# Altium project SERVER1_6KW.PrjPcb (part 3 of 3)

## Sheet 7.SchDoc
size 420 x 297 mm
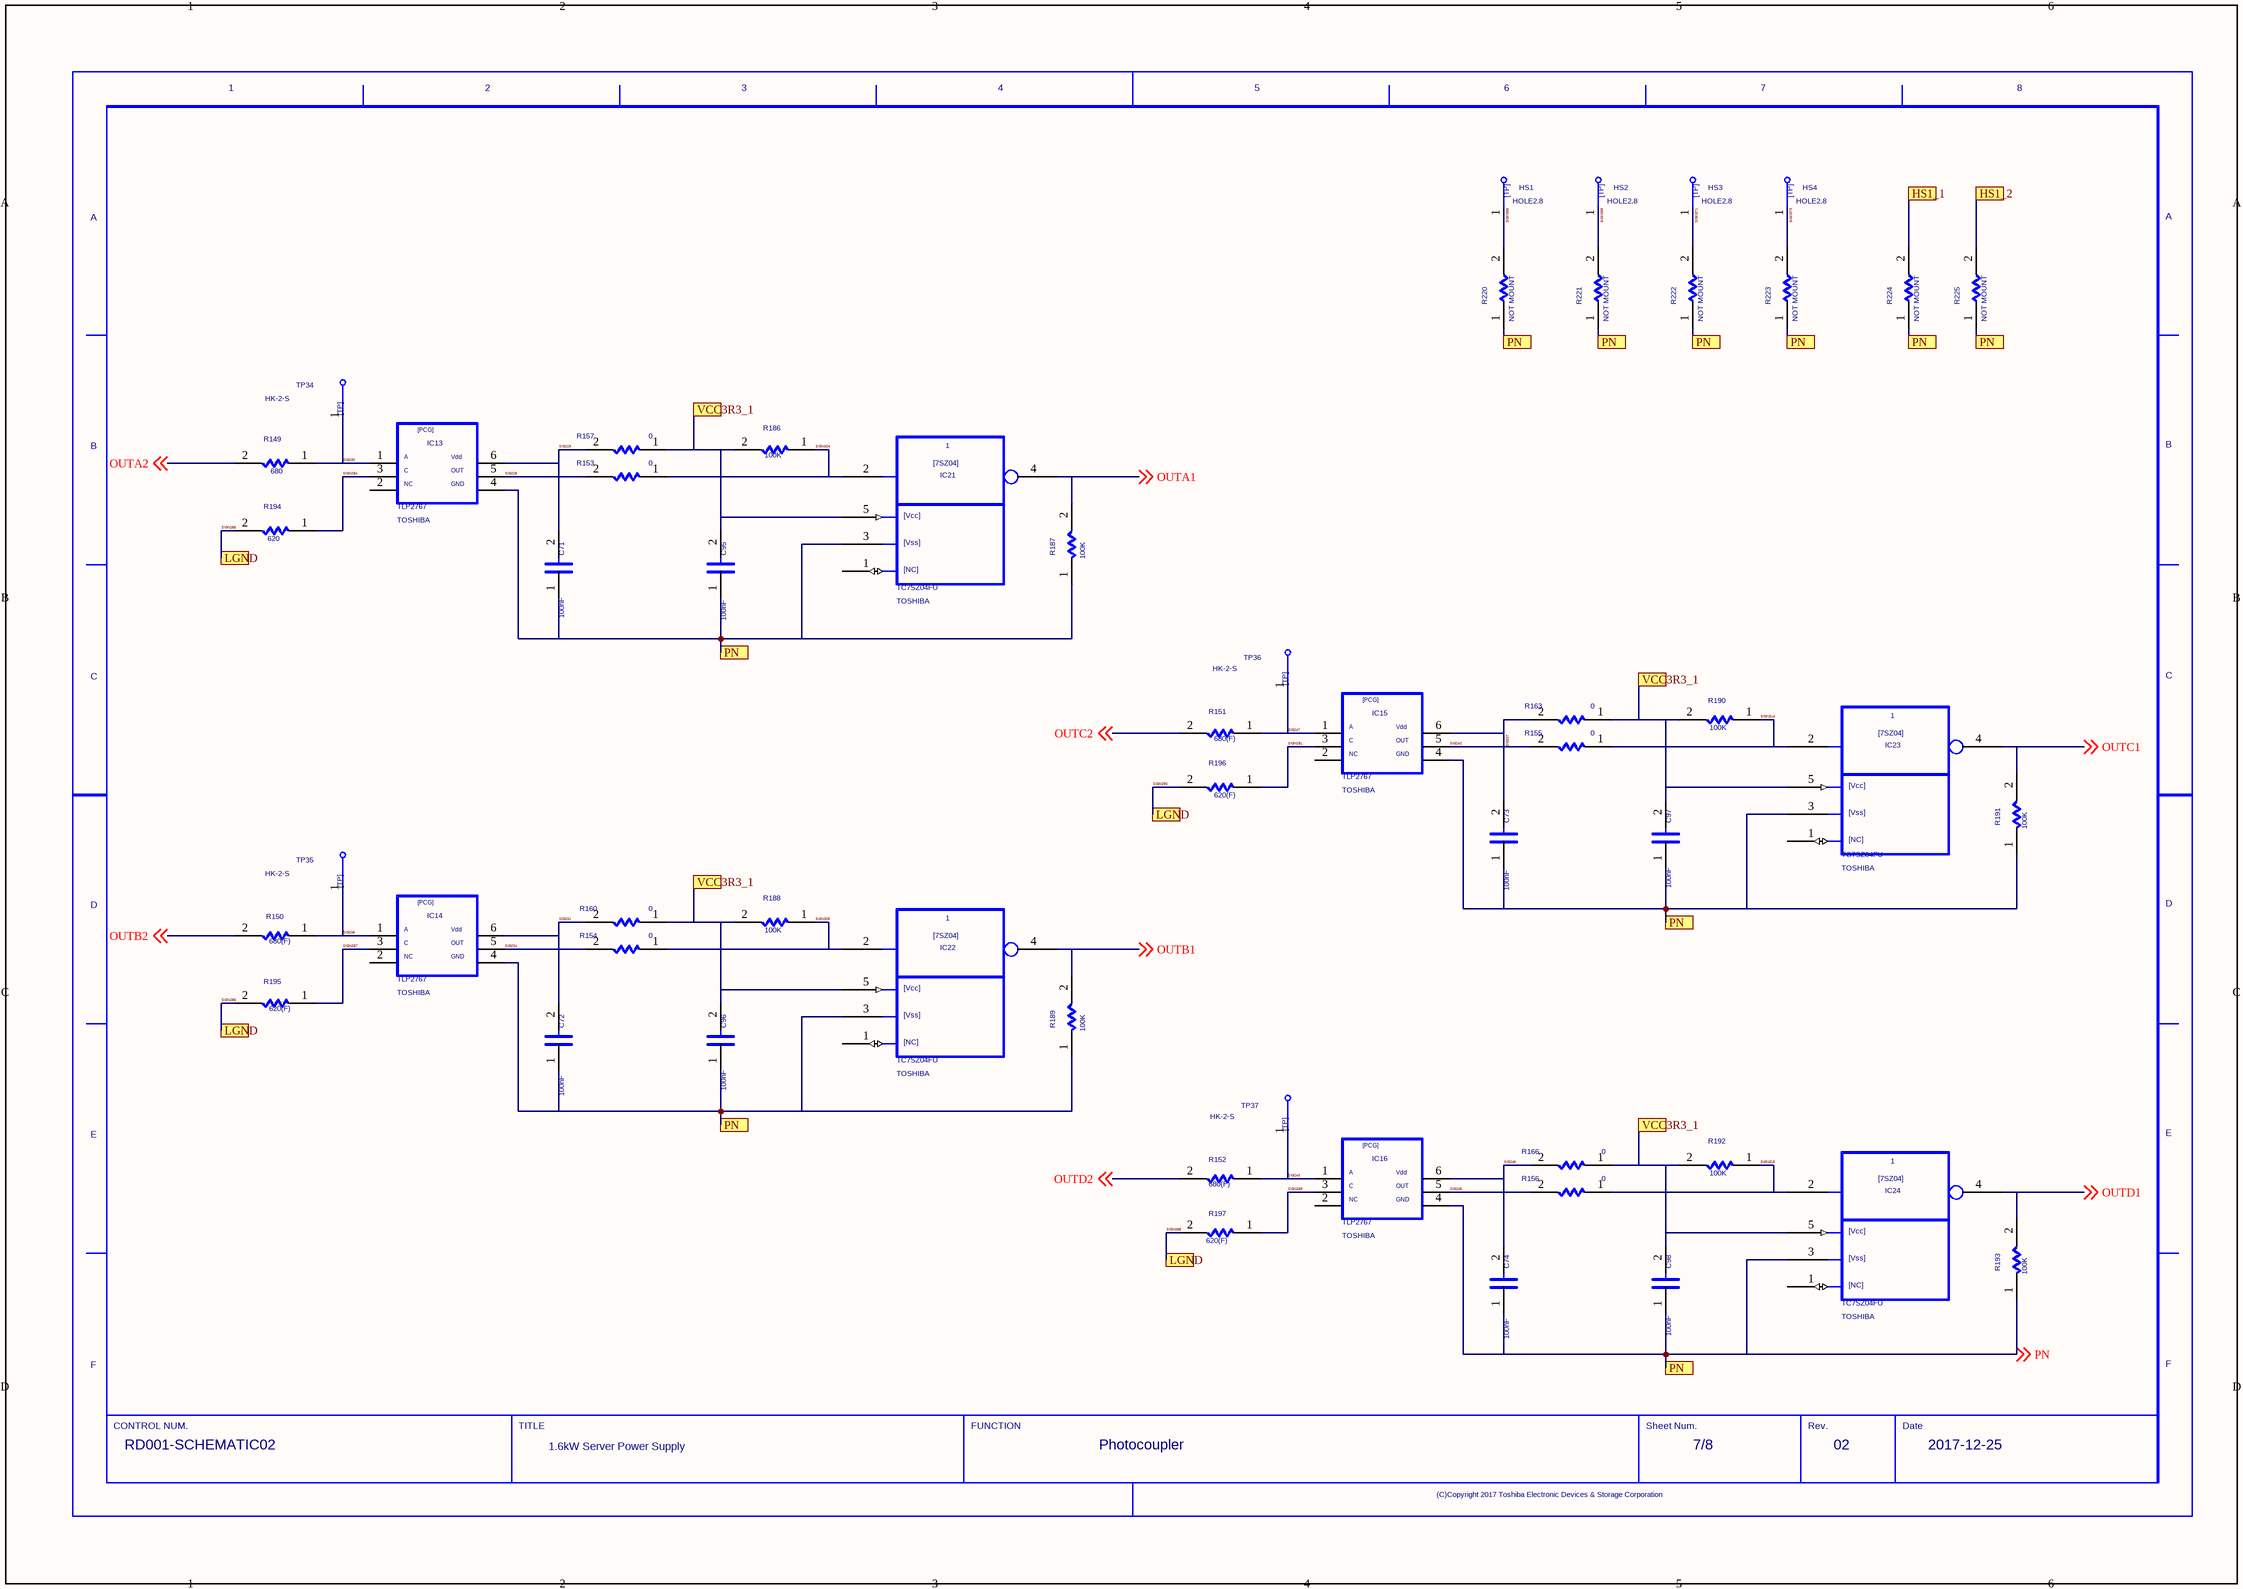
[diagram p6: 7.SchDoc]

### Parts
(Parts that share a designator on the sheet are numbered #1, #2 ... from top to bottom, then left to right.)
C71  VAL1: 100nF  (hidden comment: C)
C72  VAL1: 100nF  (hidden comment: C)
C73  VAL1: 100nF  (hidden comment: C)
C74  VAL1: 100nF  (hidden comment: C)
C95  VAL1: 100nF  (hidden comment: C)
C96  VAL1: 100nF  (hidden comment: C)
C97  VAL1: 100nF  (hidden comment: C)
C98  VAL1: 100nF  (hidden comment: C)
HS1  VAL3: HOLE2.8  (hidden comment: TP)
HS2  VAL3: HOLE2.8  (hidden comment: TP)
HS3  VAL3: HOLE2.8  (hidden comment: TP)
HS4  VAL3: HOLE2.8  (hidden comment: TP)
IC13  USERCOMPTEXT3: TOSHIBA  VAL3: TLP2767  (hidden comment: PCG6PIN)
IC14  USERCOMPTEXT3: TOSHIBA  VAL3: TLP2767  (hidden comment: PCG6PIN)
IC15  USERCOMPTEXT3: TOSHIBA  VAL3: TLP2767  (hidden comment: PCG6PIN)
IC16  USERCOMPTEXT3: TOSHIBA  VAL3: TLP2767  (hidden comment: PCG6PIN)
IC21  USERCOMPTEXT3: TOSHIBA  VAL3: TC7SZ04FU  (hidden comment: 7SZ04)
IC22  USERCOMPTEXT3: TOSHIBA  VAL3: TC7SZ04FU  (hidden comment: 7SZ04)
IC23  USERCOMPTEXT3: TOSHIBA  VAL3: TC7SZ04FU  (hidden comment: 7SZ04)
IC24  USERCOMPTEXT3: TOSHIBA  VAL3: TC7SZ04FU  (hidden comment: 7SZ04)
R149  VAL1: 680  (hidden comment: R)
R150  VAL1: 680(F)  (hidden comment: R)
R151  VAL1: 680(F)  (hidden comment: R)
R152  VAL1: 680(F)  (hidden comment: R)
R153  VAL1: 0  (hidden comment: R)
R154  VAL1: 0  (hidden comment: R)
R155  VAL1: 0  (hidden comment: R)
R156  VAL1: 0  (hidden comment: R)
R157  VAL1: 0  (hidden comment: R)
R160  VAL1: 0  (hidden comment: R)
R163  VAL1: 0  (hidden comment: R)
R166  VAL1: 0  (hidden comment: R)
R186  VAL1: 100K  (hidden comment: R)
R187  VAL1: 100K  (hidden comment: R)
R188  VAL1: 100K  (hidden comment: R)
R189  VAL1: 100K  (hidden comment: R)
R190  VAL1: 100K  (hidden comment: R)
R191  VAL1: 100K  (hidden comment: R)
R192  VAL1: 100K  (hidden comment: R)
R193  VAL1: 100K  (hidden comment: R)
R194  VAL1: 620  (hidden comment: R)
R195  VAL1: 620(F)  (hidden comment: R)
R196  VAL1: 620(F)  (hidden comment: R)
R197  VAL1: 620(F)  (hidden comment: R)
R220  NOTMOUNT: NOT MOUNT  (hidden comment: R)
R221  NOTMOUNT: NOT MOUNT  (hidden comment: R)
R222  NOTMOUNT: NOT MOUNT  (hidden comment: R)
R223  NOTMOUNT: NOT MOUNT  (hidden comment: R)
R224  NOTMOUNT: NOT MOUNT  (hidden comment: R)
R225  NOTMOUNT: NOT MOUNT  (hidden comment: R)
TP34  VAL3: HK-2-S  (hidden comment: TP)
TP35  VAL3: HK-2-S  (hidden comment: TP)
TP36  VAL3: HK-2-S  (hidden comment: TP)
TP37  VAL3: HK-2-S  (hidden comment: TP)
U?#7  DATE: 2017-12-25  TITLE: 1.6kW Server Power Supply  REVISION: 02  SHEETNUMBER: 7/8  DRAWINGNUMBER: RD001-SCHEMATIC02  FUNCTION: Photocoupler  (hidden comment: WAKU_DEF100)

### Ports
HS1_1, HS1_2, LGND, PN, VCC3R3_1

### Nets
OUTA1: IC21.4 R187.2 ; off-sheet OUTA1
OUTA2: R149.2 ; off-sheet OUTA2
OUTB1: IC22.4 R189.2 ; off-sheet OUTB1
OUTB2: R150.2 ; off-sheet OUTB2
OUTC1: IC23.4 R191.2 ; off-sheet OUTC1
OUTC2: R151.2 ; off-sheet OUTC2
OUTD1: IC24.4 R193.2 ; off-sheet OUTD1
OUTD2: R152.2 ; off-sheet OUTD2
PN: C71.1 C72.1 C73.1 C74.1 C95.1 C96.1 C97.1 C98.1 IC13.4 IC14.4 IC15.4 IC16.4 IC21.3 IC22.3 IC23.3 IC24.3 R187.1 R189.1 R191.1 R193.1 R220.1 R221.1 R222.1 R223.1 R224.1 R225.1 ; off-sheet PN, port PN  [project net SIGN347]
SIG228: IC13.5 R153.2
SIG229: C71.2 IC13.6 R157.2
SIG230: IC13.1 R149.1 TP34.1
SIG231: C72.2 IC14.6 R160.2
SIG234: IC14.5 R154.2
SIG236: IC14.1 R150.1 TP35.1
SIG237: C73.2 IC15.6 R163.2
SIG242: IC15.5 R155.2
SIG243: IC16.1 R152.1 TP37.1
SIG245: IC16.5 R156.2
SIG246: C74.2 IC16.6 R166.2
SIG247: IC15.1 R151.1 TP36.1
SIGN284: IC13.3 R194.1
SIGN285: R194.2 R195.2 R196.2 R197.2 ; port LGND  [also labelled SIGN286, SIGN288, SIGN290]  [project net SIG439]
SIGN287: IC14.3 R195.1
SIGN289: IC16.3 R197.1
SIGN291: IC15.3 R196.1
SIGN304: IC21.2 R153.1 R186.1
SIGN305: IC22.2 R154.1 R188.1
SIGN314: IC23.2 R155.1 R190.1
SIGN315: IC24.2 R156.1 R192.1
SIGN366: HS1.1 R220.2
SIGN369: HS2.1 R221.2
SIGN371: HS3.1 R222.2
SIGN373: HS4.1 R223.2
VCC3R3_1: C95.2 C96.2 C97.2 C98.2 IC21.5 IC22.5 IC23.5 IC24.5 R157.1 R160.1 R163.1 R166.1 R186.2 R188.2 R190.2 R192.2 ; port VCC3R3_1
NetR224_2: R224.2 ; port HS1_1
NetR225_2: R225.2 ; port HS1_2

Not connected (* = marked no-connect by the designer): IC13 2; IC14 2; IC15 2; IC16 2; IC21 1; IC22 1; IC23 1; IC24 1

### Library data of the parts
C71-C74 = C: SQ_PART_MODEL: CON_100N; OriginalSymbolOrigin: (2540,7620); COMP: PRT_52; VAL3: C1005X7R1E104K050BB; MAKER: TDK; CHIPSIZE: 1005; VAL2: 25V,±10%; RATEDVOLTAGE: 25; MAXGCOUNT: 1; OUMEMAKER: MRT 村田製作所; FNLEADFREETHET1GT2GMCTH1: N_N_N; OUMECLASSIFICATION: セラミックコンデンサ; NOMINALCAPACITA: 100n; ADSCNVFLAG: ON; OUMEMAKERKATAMEI: GRM155R71E104KE14D; ADSCOMPONENTNAME: C_1005; CAPACITANCETOLE: K; CDMASTERCADCELG: KC0005; ADSMODELNAME: s_GRM155R71E104KE14D
C95-C98 = C: OriginalSymbolOrigin: (2540,7620); COMP: PRT_52; VAL3: C1005X7R1E104K050BB; MAKER: TDK; CHIPSIZE: 1005; VAL2: 25V,±10%; RATEDVOLTAGE: 25; MAXGCOUNT: 1; NOMINALCAPACITA: 100n; ADSCOMPONENTNAME: C_1005; CAPACITANCETOLE: K; ADSMODELNAME: s_GRM155R71E104KE14D
HS1-HS4 = TP: TIME: 16:12:21; UPDATEUSER: fukuda-y; UPDATETIME: 16:18:11; SAVECOUNT: 2; SAVEAREA0: -242,-92,12810,7836; OriginalSymbolOrigin: (0,7620); COMP: PRT_39; CHIPSIZE: Through Hole
IC13-IC16 = PCG6PIN: TIME: 11:12:30; UPDATEUSER: s.maruyama; UPDATETIME: 11:21:41; SAVECOUNT: 5; SAVEAREA0: -4197,-437,28946,21425; OriginalSymbolOrigin: (5080,17780); COMP: PRT_15
IC21-IC24 = 7SZ04: SAVEAREA0: -11095,0,51836,33020; TIME: 16:23:49; UPDATEUSER: s.maruyama; UPDATETIME: 20:33:11; SAVECOUNT: 7; OriginalSymbolOrigin: (7620,30480); COMP: PRT_2
R149 = R: OriginalSymbolOrigin: (5080,5080); COMP: PRT_8; VAL3: RK73H1JTTD6800F; MAKER: KOA; CHIPSIZE: 1608; VAL2: 100mW,±1%
R150-R152 = R: OriginalSymbolOrigin: (5080,5080); COMP: PRT_8; VAL3: RK73H1JTTD6800F; MAKER: KOA; CHIPSIZE: 1608; VAL2: 100mW
R153-R157 R160 R163 R166 = R: SQ_PART_MODEL: RES_0; OriginalSymbolOrigin: (5080,5080); COMP: PRT_8; VAL3: RK73Z1JTTD; MAKER: KOA; CHIPSIZE: 1608; VAL2: 100mW; MAXGCOUNT: 1; OUMEMAKER: NAE パナソニックエレクトロニックデバイス; MOUNTINGFORMSMD: SMD; FNLEADFREETHET1GT2GMCTH1: 2_1_N; OUMECLASSIFICATION: 表面実装用固定抵抗器; SIZECODESMD: 1005; RESISTANCETOLER: X; PMPRODUCTSTYPEG: HD1-PC1; ADSCNVFLAG: ON; POWERRATING: 63m; OUMEMAKERKATAMEI: ERJ2GE0R00X; ADSCOMPONENTNAME: R_1005; CDMASTERCADCELG: KC0005; ADSMODELNAME: s_ERJ2GE0R00X
R186-R193 = R: OriginalSymbolOrigin: (5080,5080); COMP: PRT_8; VAL3: RK73B1JTTD104J; MAKER: KOA; CHIPSIZE: 1608; VAL2: 100mW,±5%
R194 = R: OriginalSymbolOrigin: (5080,5080); COMP: PRT_8; VAL3: ERJ-3EKF6200V; MAKER: PANASONIC; CHIPSIZE: 1608; VAL2: 100mW,±1%
R195-R197 = R: OriginalSymbolOrigin: (5080,5080); COMP: PRT_8; VAL3: ERJ-3EKF6200V; MAKER: PANASONIC; CHIPSIZE: 1608; VAL2: 100mW
R220-R225 = R: SQ_PART_MODEL: RES_0; OriginalSymbolOrigin: (5080,5080); COMP: PRT_8; VAL3: RK73Z1JTTD; VAL2: 100mW; MAKER: KOA; CHIPSIZE: 1608; VAL1: 0; MAXGCOUNT: 1; OUMEMAKER: HDK 北陸電気工業; MOUNTINGFORMSMD: SMD; FNLEADFREETHET1GT2GMCTH1: N_N_N; OUMECLASSIFICATION: 表面実装用固定抵抗器; SIZECODESMD: 1005; RESISTANCETOLER: X; ADSCNVFLAG: ON; POWERRATING: 63m; OUMEMAKERKATAMEI: CR10-000V; ADSCOMPONENTNAME: R_1005; CDMASTERCADCELG: KC0005; ADSMODELNAME: s_CR10_000V
TP34-TP37 = TP: TIME: 16:12:21; UPDATEUSER: fukuda-y; UPDATETIME: 16:18:11; SAVECOUNT: 2; SAVEAREA0: -242,-92,12810,7836; OriginalSymbolOrigin: (0,7620); COMP: PRT_44; MAKER: MAC8
U?#7 = WAKU_DEF100: PLOTTIME: HH:MM; SAVEAREA0: -45080,-4508,463680,304612; TIME: 18:12:27; UPDATEUSER: f1043010; UPDATETIME: 13:49:58; SAVECOUNT: 3; OriginalSymbolOrigin: (10160,284480); PAGENUMBER: 7; DESIGNED: TOSHIBA

## Sheet 8.SchDoc
size 420 x 297 mm
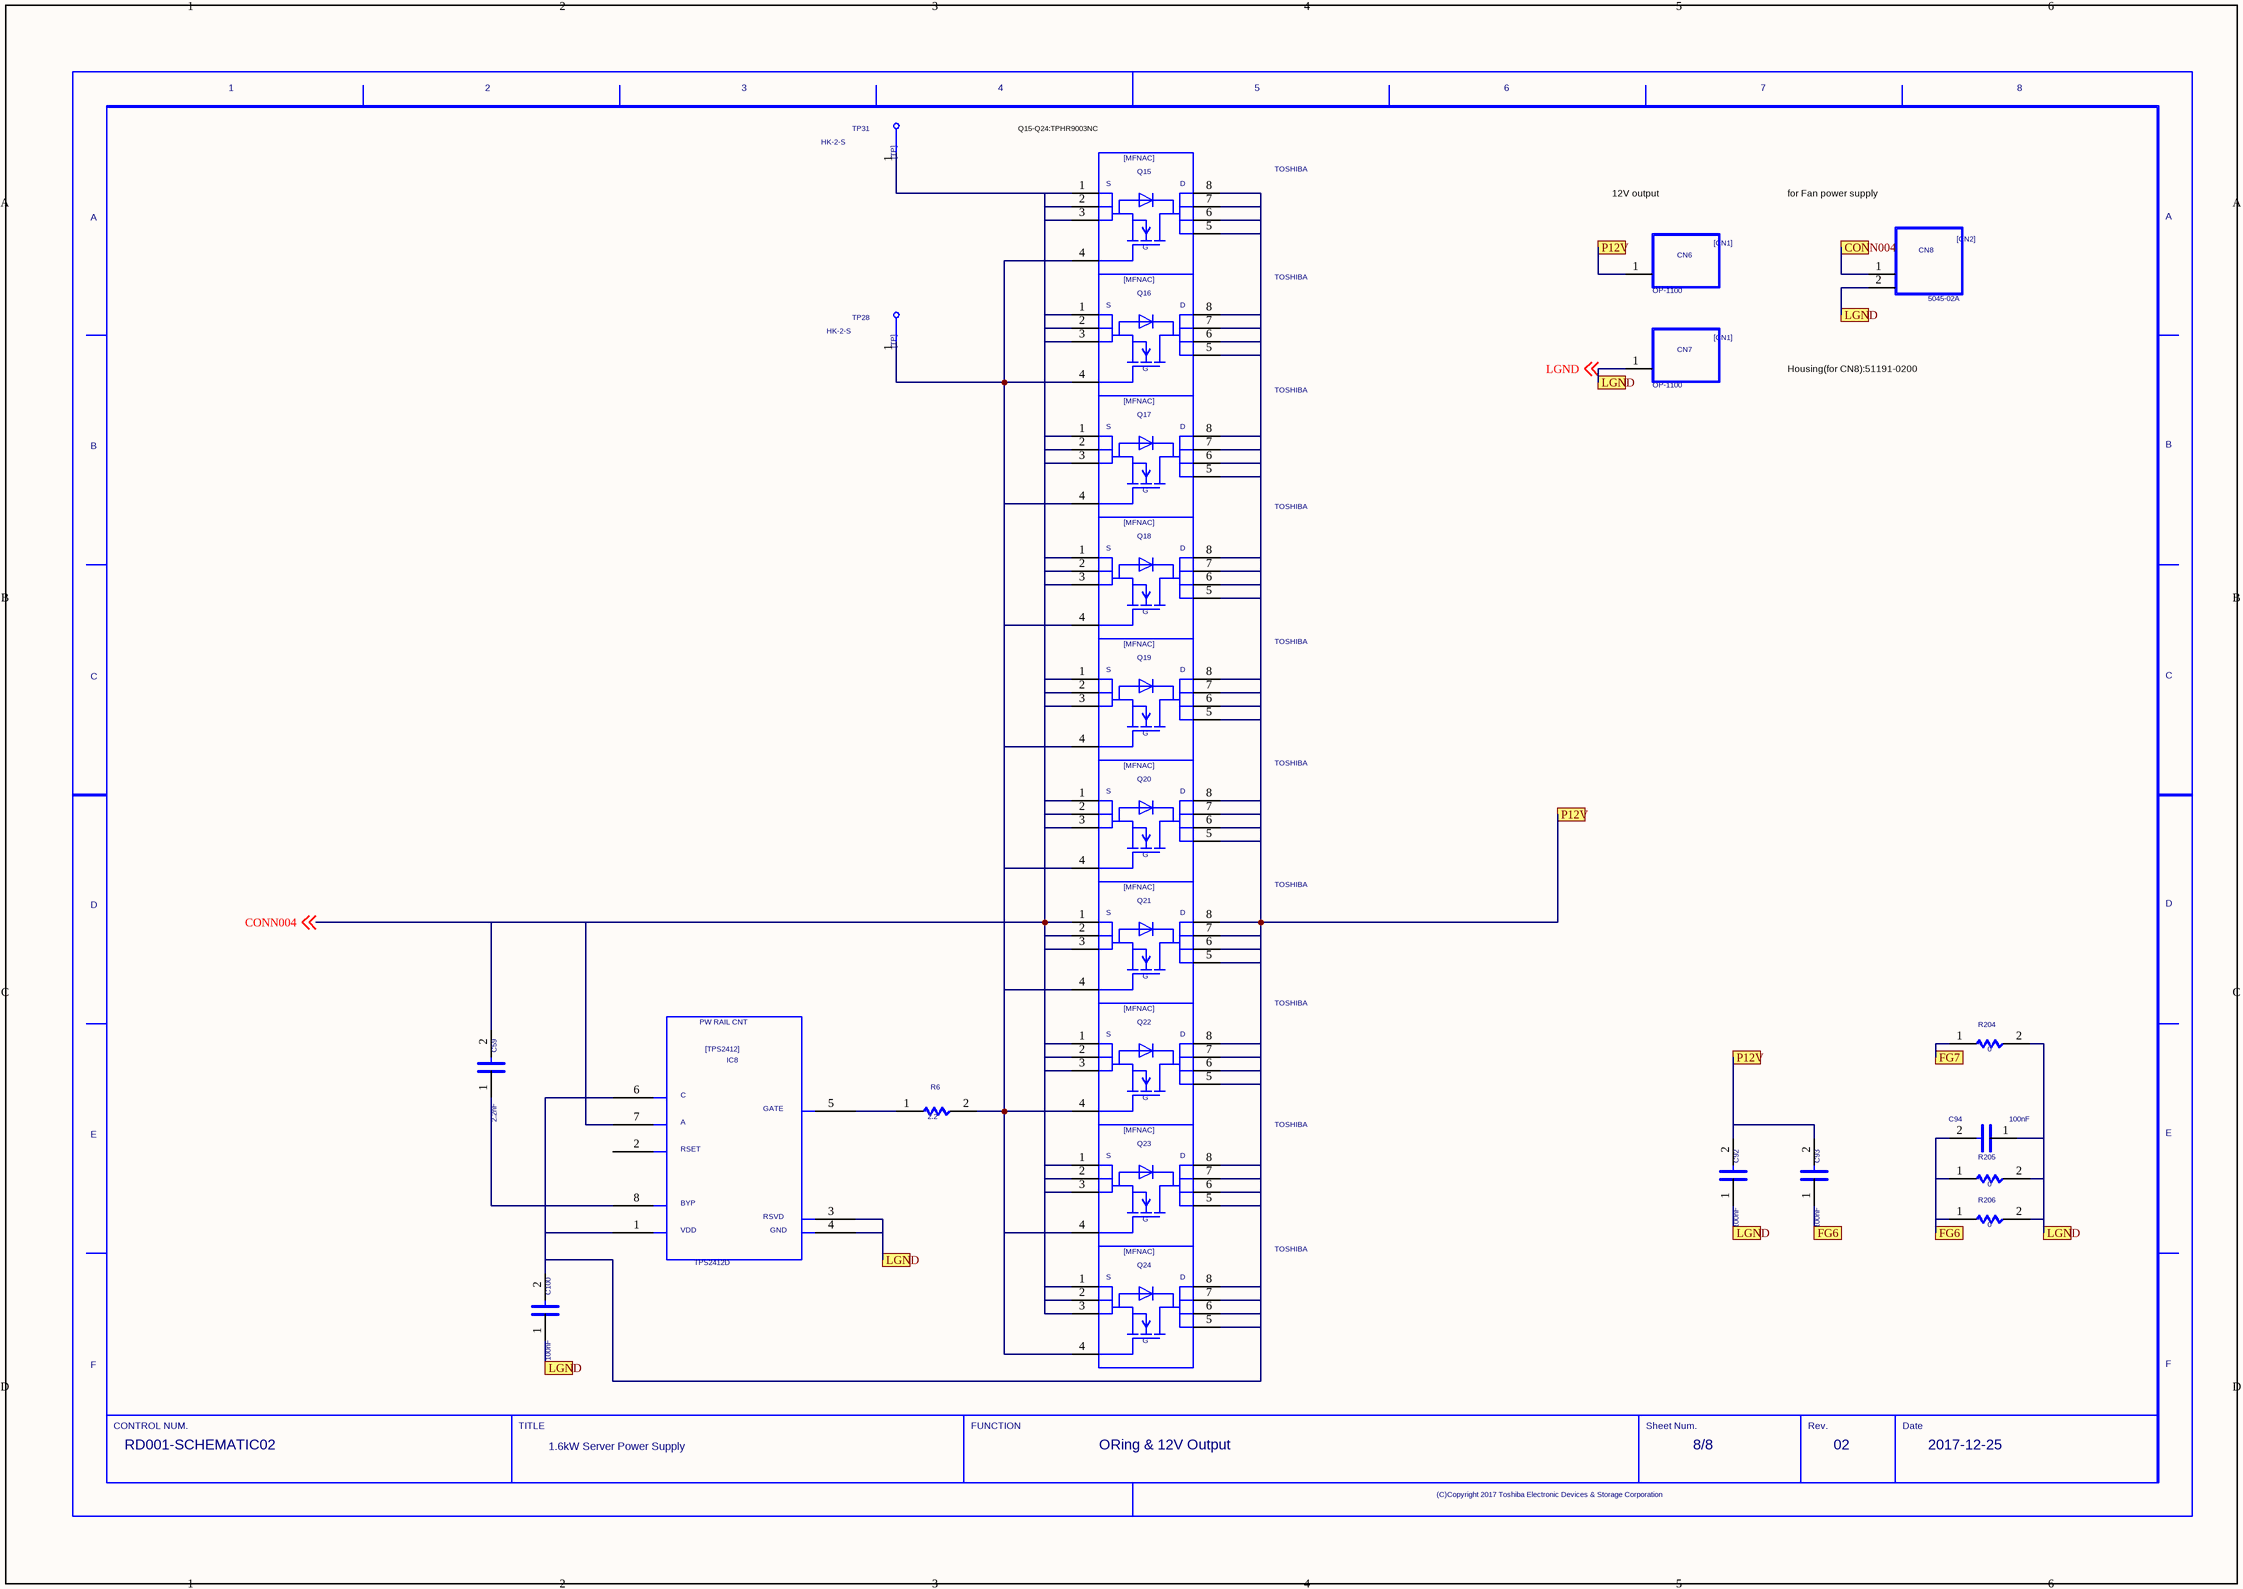
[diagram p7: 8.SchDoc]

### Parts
(Parts that share a designator on the sheet are numbered #1, #2 ... from top to bottom, then left to right.)
C59  VAL1: 2.2nF  (hidden comment: C)
C92  VAL1: 100nF  (hidden comment: C)
C93  VAL1: 100nF  (hidden comment: C)
C94  VAL1: 100nF  (hidden comment: C)
C100  VAL1: 100nF  (hidden comment: C)
CN6  VAL3: OP-1100  (hidden comment: CN1)
CN7  VAL3: OP-1100  (hidden comment: CN1)
CN8  VAL3: 5045-02A  (hidden comment: CN2)
IC8  VAL3: TPS2412D  (hidden comment: L2412)
Q15  USERCOMPTEXT3: TOSHIBA  (hidden comment: MFNAC)
Q16  USERCOMPTEXT3: TOSHIBA  (hidden comment: MFNAC)
Q17  USERCOMPTEXT3: TOSHIBA  (hidden comment: MFNAC)
Q18  USERCOMPTEXT3: TOSHIBA  (hidden comment: MFNAC)
Q19  USERCOMPTEXT3: TOSHIBA  (hidden comment: MFNAC)
Q20  USERCOMPTEXT3: TOSHIBA  (hidden comment: MFNAC)
Q21  USERCOMPTEXT3: TOSHIBA  (hidden comment: MFNAC)
Q22  USERCOMPTEXT3: TOSHIBA  (hidden comment: MFNAC)
Q23  USERCOMPTEXT3: TOSHIBA  (hidden comment: MFNAC)
Q24  USERCOMPTEXT3: TOSHIBA  (hidden comment: MFNAC)
R6  VAL1: 2.2  (hidden comment: R)
R204  VAL1: 0  (hidden comment: R)
R205  VAL1: 0  (hidden comment: R)
R206  VAL1: 0  (hidden comment: R)
TP28  VAL3: HK-2-S  (hidden comment: TP)
TP31  VAL3: HK-2-S  (hidden comment: TP)
U?#8  DATE: 2017-12-25  TITLE: 1.6kW Server Power Supply  REVISION: 02  SHEETNUMBER: 8/8  DRAWINGNUMBER: RD001-SCHEMATIC02  FUNCTION: ORing & 12V Output  (hidden comment: WAKU_DEF100)

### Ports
CONN004, FG6, FG7, LGND, P12V

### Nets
CONN004: C59.2 IC8.7 Q15.1 Q15.2 Q15.3 Q16.1 Q16.2 Q16.3 Q17.1 Q17.2 Q17.3 Q18.1 Q18.2 Q18.3 Q19.1 Q19.2 Q19.3 Q20.1 Q20.2 Q20.3 Q21.1 Q21.2 Q21.3 Q22.1 Q22.2 Q22.3 Q23.1 Q23.2 Q23.3 Q24.1 Q24.2 Q24.3 TP31.1 ; off-sheet CONN004
LGND: C92.1 C94.1 C100.1 CN7.1 CN8.2 IC8.3 IC8.4 R204.2 R205.2 R206.2 ; off-sheet LGND, port LGND  [project net SIG439]
SIG122: C59.1 IC8.8
SIG136: IC8.5 R6.1
SIG141: Q15.4 Q16.4 Q17.4 Q18.4 Q19.4 Q20.4 Q21.4 Q22.4 Q23.4 Q24.4 R6.2 TP28.1
NetC92_2: C92.2 C93.2 C100.2 CN6.1 IC8.1 IC8.6 Q15.5 Q15.6 Q15.7 Q15.8 Q16.5 Q16.6 Q16.7 Q16.8 Q17.5 Q17.6 Q17.7 Q17.8 Q18.5 Q18.6 Q18.7 Q18.8 Q19.5 Q19.6 Q19.7 Q19.8 Q20.5 Q20.6 Q20.7 Q20.8 Q21.5 Q21.6 Q21.7 Q21.8 Q22.5 Q22.6 Q22.7 Q22.8 Q23.5 Q23.6 Q23.7 Q23.8 Q24.5 Q24.6 Q24.7 Q24.8 ; port P12V
NetC93_1: C93.1 C94.2 R205.1 R206.1 ; port FG6
NetCN8_1: CN8.1 ; port CONN004
NetR204_1: R204.1 ; port FG7

Not connected (* = marked no-connect by the designer): IC8 2

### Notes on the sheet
- Q15-Q24:TPHR9003NC
- 12V output
- for Fan power supply
- Housing(for CN8):51191-0200

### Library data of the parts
C59 = C: SQ_PART_MODEL: CON_2.2N; OriginalSymbolOrigin: (2540,7620); COMP: PRT_52; TEMPCHARACTERI2: B; VAL3: UMK105BJ222KV-F; MAKER: TDK; CHIPSIZE: 1005; VAL2: 50V,±10%; PMPRODUCTSTYPEG: HD1-PC1; RATEDVOLTAGE: 50; MAXGCOUNT: 1; OUMEMAKER: TYD 太陽誘電; FNLEADFREETHET1GT2GMCTH1: 2_0_N; OUMECLASSIFICATION: セラミックコンデンサ; NOMINALCAPACITA: 2.2n; ADSCNVFLAG: ON; ADSCOMPONENTNAME: C_1005; CAPACITANCETOLE: K; CDMASTERCADCELG: KC0005; ADSMODELNAME: s_UMK105BJ222KV_F
C92-C94 = C: OriginalSymbolOrigin: (2540,7620); VAL3: C1005X7R1E104K050BB; FNLEADFREETHET1GT2GMCTH1: N_N_N; CDMASTERCADCELG: KC0005; OUMEMAKER: MRT 村田製作所; OUMEMAKERKATAMEI: GRM155R71E104KE14D; OUMECLASSIFICATION: セラミックコンデンサ; QUADMODEL: CON_100N; COMP: PRT_52; MAKER: TDK; CHIPSIZE: 1005; VAL2: 25V,±10%; RATEDVOLTAGE: 25; MAXGCOUNT: 1; NOMINALCAPACITA: 100n; CAPACITANCETOLE: K; ADSMODELNAME: s_GRM155R71E104KE14D
C100 = C: OriginalSymbolOrigin: (2540,7620); COMP: PRT_52; VAL3: C1005X7R1E104K050BB; MAKER: TDK; CHIPSIZE: 1005; VAL2: 25V,±10%; PMPRODUCTSTYPEG: HD1; RATEDVOLTAGE: 50; MAXGCOUNT: 1; OUMEMAKER: MRT 村田製作所; QUADMODEL: CON_2.2N; FNLEADFREETHET1GT2GMCTH1: 2_0_N; OUMECLASSIFICATION: セラミックコンデンサ; NOMINALCAPACITA: 2.2n; OUMEMAKERKATAMEI: GRM155R71H222KA01D; CAPACITANCETOLE: K; CDMASTERCADCELG: KC0005; ADSMODELNAME: s_GRM155R71H222KA01D
CN6 CN7 = CN1: OriginalSymbolOrigin: (2540,12700); MAKER: OSADA; COMP: PRT_38
CN8 = CN2: OriginalSymbolOrigin: (2540,15240); MAKER: MOLEX; COMP: PRT_42
IC8 = L2412: SAVEAREA0: -16399,-622,62276,51274; TIME: 11:49:52; UPDATEUSER: cae; UPDATETIME: 09:49:41; SAVECOUNT: 36; OriginalSymbolOrigin: (7620,48260); MAKER: TEXAS; COMP: PRT_62
Q15-Q24 = MFNAC: TIME: 18:29:30; UPDATEUSER: 19990028; UPDATETIME: 14:45:16; SAVECOUNT: 26; SAVEAREA0: -10143,-336,37609,28718; OriginalSymbolOrigin: (5080,25400); VAL3: TPHR9003NC; COMP: PRT_60
R6 = R: OriginalSymbolOrigin: (5080,5080); COMP: PRT_8; MAKER: KAMAYA; VAL3: RMC1/16 - 2R2J TP; CHIPSIZE: 1608; VAL2: 100mW,±5%; MAXGCOUNT: 1; OUMEMAKER: YGO ヤゲオ; QUADMODEL: RES_2.2; MOUNTINGFORMSMD: SMD; FNLEADFREETHET1GT2GMCTH1: 2_1_N; OUMECLASSIFICATION: 表面実装用固定抵抗器; RESISTANCETOLER: J; PMPRODUCTSTYPEG: PC1; POWERRATING: 100m; OUMEMAKERKATAMEI: RC0603JR-072R2L; CDMASTERCADCELG: KC0008; ADSMODELNAME: s_RC0603JR_072R2L
R204-R206 = R: OriginalSymbolOrigin: (5080,5080); POWERRATING: 100m; RESISTANCETOLER: X; PMPRODUCTSTYPEG: DME-HD1-PC1; FNLEADFREETHET1GT2GMCTH1: 3_2_N; CDMASTERCADCELG: KCK0203; OUMEMAKER: KOA コーア; OUMEMAKERKATAMEI: RK73Z1JTTD; OUMECLASSIFICATION: 表面実装用固定抵抗器; QUADMODEL: RES_0; COMP: PRT_8; MAKER: KOA; CHIPSIZE: 1608; VAL2: 100mW; MAXGCOUNT: 1; MOUNTINGFORMSMD: SMD; ADSMODELNAME: s_RK73Z1JTTD
TP28 TP31 = TP: as TP34-TP37 on sheet 7
U?#8 = WAKU_DEF100: PLOTTIME: HH:MM; SAVEAREA0: -45080,-4508,463680,304612; TIME: 12:01:09; UPDATEUSER: f1043010; UPDATETIME: 13:49:58; SAVECOUNT: 3; OriginalSymbolOrigin: (10160,284480); PAGENUMBER: 8; DESIGNED: TOSHIBA

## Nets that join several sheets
CONN002: 4 (6 pins), 5 (T5.1 T6.1)
CONN003: 4 (D18.C D19.A L3.2), 5 (T5.2 T6.2)
CONN004: 5 (20 pins), 6 (R75.2), 8 (33 pins)
CS: 4 (D14.C), 6 (R67.2 R185.2)
CSA: 2 (5 pins), 3 (R170.1)
CSB: 2 (5 pins), 3 (R169.1)
GDA: 2 (C81.2 IC2.2), 3 (IC3.14 TP5.1)
GDB: 2 (C80.2 IC2.4), 3 (IC3.17 TP6.1)
OUTA1: 4 (R111.1), 7 (IC21.4 R187.2)
OUTA2: 6 (IC10.22), 7 (R149.2)
OUTB1: 4 (R110.1), 7 (IC22.4 R189.2)
OUTB2: 6 (IC10.21), 7 (R150.2)
OUTC1: 4 (R113.1), 7 (IC23.4 R191.2)
OUTC2: 6 (IC10.20), 7 (R151.2)
OUTD1: 4 (R112.1), 7 (IC24.4 R193.2)
OUTD2: 6 (IC10.19), 7 (R152.2)
OUTE: 5 (IC6.2 IC7.2 TP23.1 TP25.1), 6 (IC10.18)
OUTF: 5 (IC6.4 IC7.4 TP24.1 TP26.1), 6 (IC10.17)
PFC_OUT: 2 (6 pins), 3 (R92.2), 4 (R178.2 T4.2)
PFC_VIN: 2 (D8.C D9.C), 3 (R95.2)
SIG6: 1 (C33.1 C63.2 C65.1 L12.4), 2 (D3.3 D9.A L2.1)
SIG8: 1 (C33.2 C65.2 IC20.3 R138.2), 2 (D3.2 D8.A L1.1)
SIG439: 4 (R9.1 T4.3), 5 (68 pins), 6 (30 pins), 7 (R194.2 R195.2 R196.2 R197.2), 8 (10 pins)
SIGN347: 1 (5 pins), 2 (21 pins), 3 (35 pins), 4 (22 pins), 7 (26 pins)
VCC3R3_1: 3 (R117.2), 7 (16 pins)
VCC12R0_1: 1 (C70.2 D48.C IC20.1), 2 (5 pins), 3 (R116.2 R120.1 R130.1), 4 (R122.1 R123.1)
VCC12R0_2: 5 (R124.1 R125.1), 6 (R49.1 R118.2)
